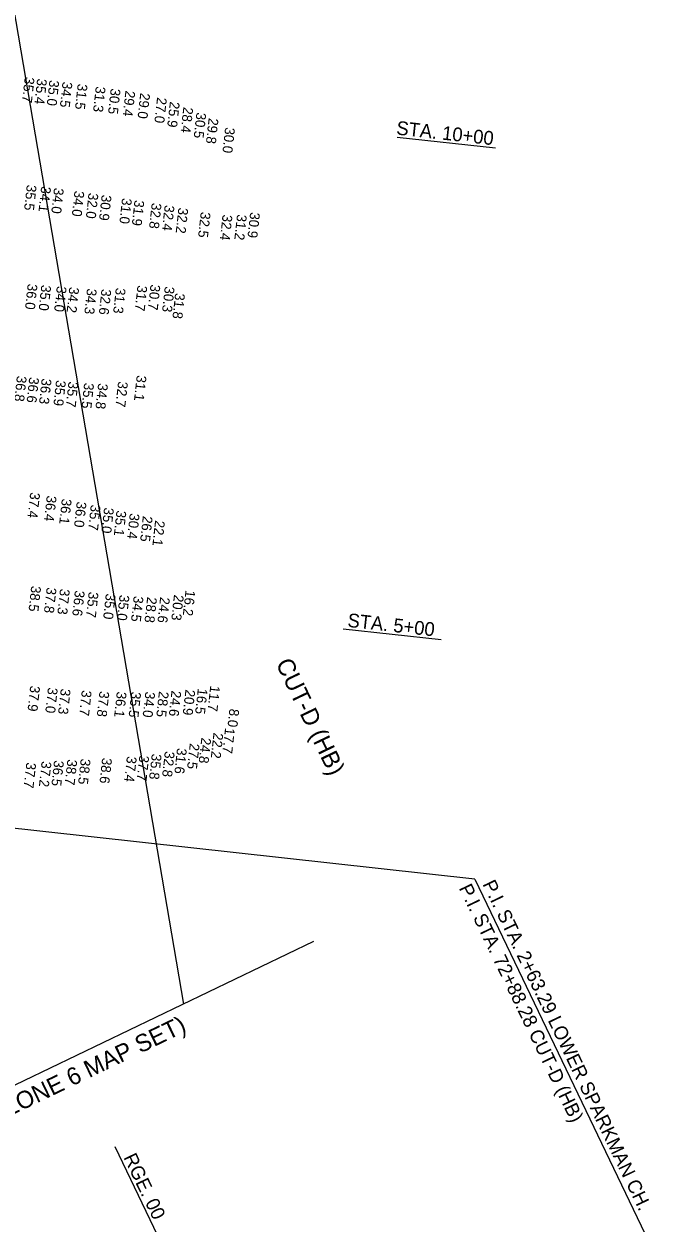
# Model space of a CAD drawing. Extents: x 508947 to 513916, y 1303283 to 1308721.
# Drawn here: x 511804 to 512436, y 1304466 to 1305678 of the extents above; entities that cross this region are included whole.
import ezdxf

# ---------------------------------------------------------------- set-up
doc = ezdxf.new("R2010")
doc.units = 0
for name, color, linetype in [('C-CHAN-WIDE', 7, 'Continuous'), ('V-ALGN-TEXT', 7, 'Continuous'), ('V-ANNO-MATC', 7, 'Continuous'), ('V-ANNO-MATC-IDEN', 7, 'Continuous'), ('V-CHAN-CNTR-IDEN', 7, 'Continuous'), ('V-TOPO-SOUN', 7, 'Continuous')]:
    doc.layers.add(name, color=color, linetype=linetype)

msp = doc.modelspace()

# ---------------------------------------------------------------- linework, layer by layer
at = {"layer": 'C-CHAN-WIDE'}
msp.add_line((511793.2, 1305694), (511965, 1304687.1), dxfattribs=at)
at = {"layer": 'V-ALGN-TEXT'}
for p, q in [((512280.6, 1305552.2), (512181.2, 1305563.1)), ((512225.9, 1305055.2), (512126.5, 1305066.1)), ((512259.9, 1304813.3), (511504.2, 1304896.6)), ((512259.9, 1304813.3), (512432.1, 1304454.8)), ((511939.1, 1304452.8), (511895.8, 1304542.9))]:
    msp.add_line(p, q, dxfattribs=at)
at = {"layer": 'V-ANNO-MATC'}
msp.add_line((512096.6, 1304750.3), (511246.3, 1304342), dxfattribs=at)

# ---------------------------------------------------------------- texts
at = {"layer": 'V-ALGN-TEXT'}
for s, rotation, p in [('STA. 10+00', 353.7132, (512179.9, 1305566.1)), ('STA. 5+00', 353.7132, (512130.5, 1305068.5)), ('P.I. STA. 2+63.29 LOWER SPARKMAN CH.', 295.6468, (512267.3, 1304808.5)), ('P.I. STA. 72+88.28 CUT-D (HB)', 295.6468, (512243.4, 1304804.5)), ('RGE. 00', 295.6468, (511904, 1304532.3))]:
    msp.add_text(s, height=13.92, rotation=rotation, dxfattribs=at).set_placement(p)
at = {"layer": 'V-ANNO-MATC-IDEN'}
msp.add_text('MATCHLINE SHEET STA. 69+00 (SEE SHEET NO. 17 ZONE 6 MAP SET)', height=17.52, rotation=25.6468, dxfattribs=at).set_placement((511261, 1304320.1))
at = {"layer": 'V-CHAN-CNTR-IDEN'}
msp.add_text('CUT-D (HB)', height=17.52, rotation=295.6468, dxfattribs=at).set_placement((512058.1, 1305031.6))
at = {"layer": 'V-TOPO-SOUN'}
for s, p in [('35.7 ', (511804.5, 1305624.6)), ('35.4 ', (511817.1, 1305623)), ('35.0 ', (511829.5, 1305621.5)), ('34.5 ', (511842.8, 1305619.8)), ('31.5 ', (511858.1, 1305617.7)), ('31.3 ', (511876.4, 1305615.1)), ('30.5 ', (511891.5, 1305613)), ('29.4 ', (511906.4, 1305610.8)), ('29.0 ', (511921.4, 1305608.5)), ('27.0 ', (511938.4, 1305604)), ('25.9 ', (511951.4, 1305599.7)), ('28.4 ', (511965, 1305594.2)), ('30.5 ', (511978.2, 1305588.7)), ('29.8 ', (511990.6, 1305583.1)), ('30.0 ', (512007.3, 1305573.7)), ('35.5 ', (511806.6, 1305515.7)), ('34.1 ', (511821.2, 1305514.1)), ('34.0 ', (511834.1, 1305512.5)), ('34.0 ', (511854.9, 1305509.6)), ('32.0 ', (511869.1, 1305507.5)), ('30.9 ', (511882.4, 1305505.5)), ('31.0 ', (511903, 1305502.2)), ('31.9 ', (511915.6, 1305500.2)), ('32.8 ', (511933, 1305497.3)), ('32.4 ', (511946.1, 1305495.1)), ('32.2 ', (511960, 1305492.5)), ('32.5 ', (511982.6, 1305488.2)), ('32.4 ', (512004.7, 1305485.5)), ('31.2 ', (512019.3, 1305485.7)), ('30.9 ', (512032.6, 1305487.9)), ('36.0 ', (511807.5, 1305415.6)), ('35.0 ', (511821.3, 1305414.4)), ('34.0 ', (511837, 1305413.2)), ('34.2 ', (511849.6, 1305412.3)), ('34.3 ', (511867.5, 1305410.8)), ('32.6 ', (511882.2, 1305410.3)), ('31.3 ', (511896.7, 1305411.5)), ('31.7 ', (511918.6, 1305414)), ('30.7 ', (511931.8, 1305414.9)), ('30.3 ', (511946.2, 1305412.9)), ('31.8 ', (511956.7, 1305406.2)), ('36.8 ', (511796.6, 1305322.6)), ('36.6 ', (511809.1, 1305321.3)), ('31.1 ', (511917.8, 1305323.1)), ('36.3 ', (511821.7, 1305319.9)), ('35.9 ', (511836.2, 1305318.1)), ('35.7 ', (511848.8, 1305316.8)), ('35.5 ', (511864.7, 1305315.5)), ('34.8 ', (511878.8, 1305315)), ('32.7 ', (511899, 1305316.9)), ('37.4 ', (511810.1, 1305204.8)), ('36.4 ', (511826.8, 1305201.5)), ('36.1 ', (511842.1, 1305198.4)), ('36.0 ', (511857.1, 1305195.4)), ('35.7 ', (511871.4, 1305192.3)), ('35.0 ', (511884.8, 1305189.4)), ('35.1 ', (511897.4, 1305186.5)), ('30.4 ', (511910.8, 1305183.6)), ('26.5 ', (511924, 1305180.9)), ('22.1 ', (511936.4, 1305176.4)), ('38.5 ', (511811.1, 1305110.3)), ('37.8 ', (511826.7, 1305108.7)), ('37.3 ', (511840.2, 1305107.3)), ('36.6 ', (511855.3, 1305105.7)), ('35.7 ', (511869.2, 1305104.2)), ('35.0 ', (511886.6, 1305102.5)), ('16.2 ', (511967.2, 1305105.9)), ('35.0 ', (511900.5, 1305101.2)), ('34.5 ', (511914.7, 1305100)), ('28.8 ', (511928.4, 1305099)), ('24.6 ', (511941.5, 1305098.9)), ('20.3 ', (511955.5, 1305101.3)), ('37.9 ', (511810.1, 1305009.4)), ('37.0 ', (511828, 1305007.6)), ('37.3 ', (511841, 1305006.4)), ('37.7 ', (511862.3, 1305004.8)), ('20.9 ', (511967.1, 1305005.5)), ('16.5 ', (511979.6, 1305006.6)), ('11.7 ', (511992.2, 1305009.4)), ('37.8 ', (511880.2, 1305003.9)), ('36.1 ', (511897.7, 1305003.4)), ('35.5 ', (511912.3, 1305003.3)), ('34.0 ', (511926.5, 1305003.3)), ('28.5 ', (511940.3, 1305003.7)), ('24.6 ', (511953, 1305004.4)), ('8.0', (512011.6, 1304986.1)), ('24.8 ', (511983.2, 1304956.9)), ('22.2 ', (511995.5, 1304961.8)), ('17.7 ', (512007.2, 1304966.8)), ('31.6 ', (511958.6, 1304946.3)), ('27.5 ', (511971.5, 1304951.1)), ('37.2 ', (511821.6, 1304933)), ('36.5 ', (511834.2, 1304933.9)), ('38.7 ', (511847.7, 1304934.9)), ('38.5 ', (511861.2, 1304935.6)), ('38.6 ', (511882.9, 1304936.5)), ('37.4 ', (511907.9, 1304938)), ('37.7 ', (511920.5, 1304939)), ('35.8 ', (511933.1, 1304940.6)), ('32.8 ', (511946.3, 1304943.1)), ('37.7 ', (511806.1, 1304931.8))]:
    msp.add_text(s, height=10, rotation=263.7131, dxfattribs=at).set_placement(p)

doc.saveas('drawing.dxf')
